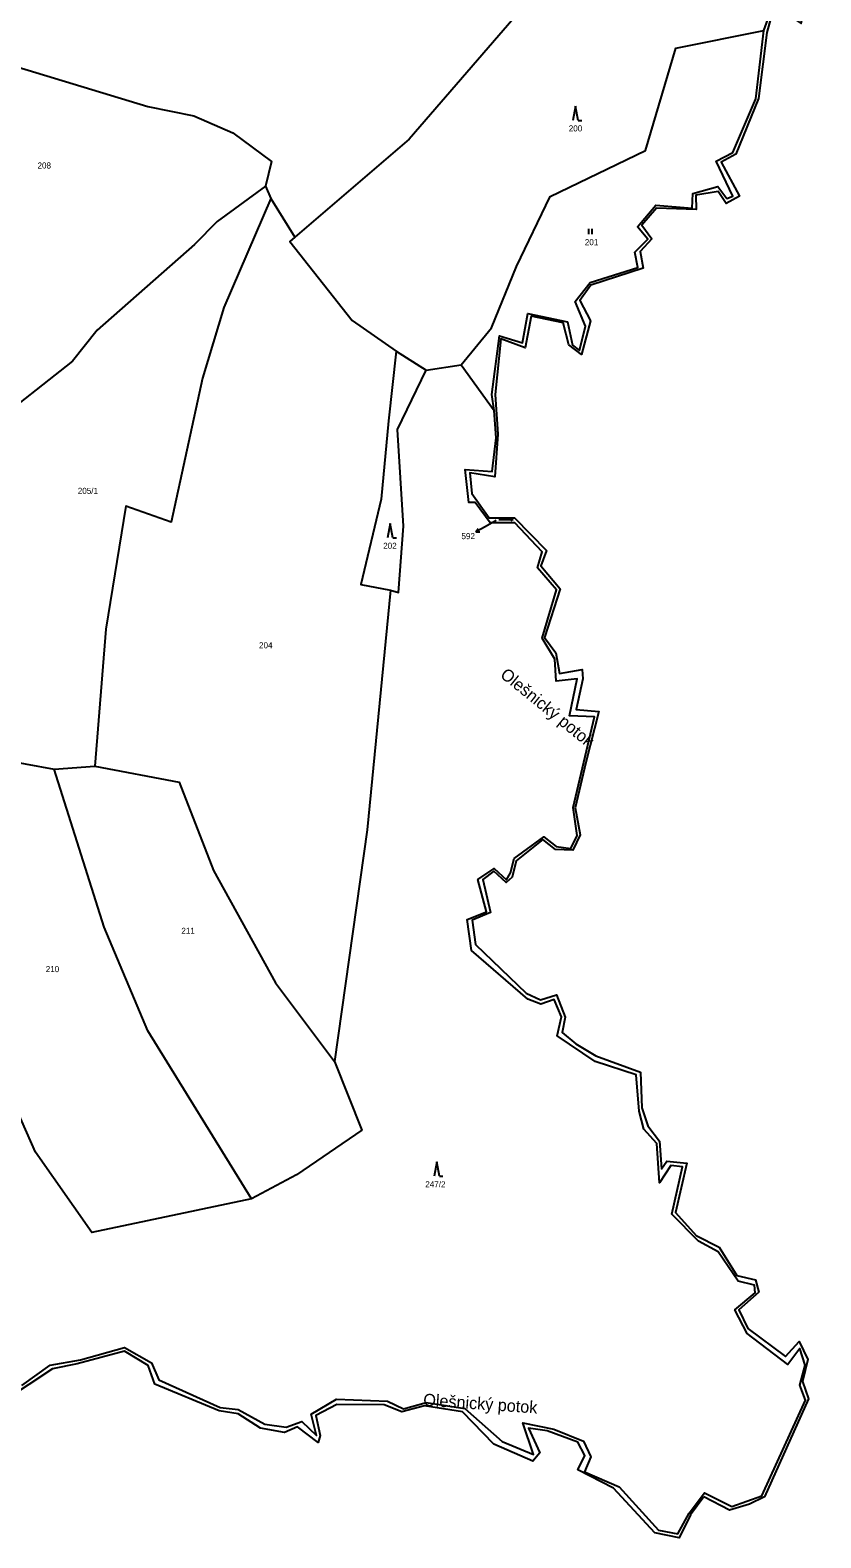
# Model space of a CAD drawing. Extents: x -680203 to -673936, y -1102717 to -1093650.
# Drawn here: x -674938.8 to -674716.8, y -1101515 to -1101091.6 of the extents above; entities that cross this region are included whole.
import ezdxf

# ---------------------------------------------------------------- set-up
doc = ezdxf.new("R2010")
doc.units = 0
for name, color, linetype in [('SOxx02xx_Staničení_Popis10', 7, 'Continuous'), ('SOxxxxxx_Koleje_hlavní_body_Popis10', 7, 'Continuous'), ('SOxxxxxx_Osa_bod_P', 7, 'Continuous'), ('x_prac', 7, 'Continuous')]:
    doc.layers.add(name, color=color, linetype=linetype)

msp = doc.modelspace()

# ---------------------------------------------------------------- linework, layer by layer
at = {"layer": 'SOxx02xx_Staničení_Popis10'}
for p, q in [((-674811.06, -1101231.09), (-674813.69, -1101232.54)), ((-674813.69, -1101232.54), (-674813.05, -1101231.62)), ((-674813.69, -1101232.54), (-674812.57, -1101232.5)), ((-674807.97, -1101229.35), (-674811.06, -1101231.09))]:
    msp.add_line(p, q, dxfattribs=at)
at = {"layer": 'SOxxxxxx_Koleje_hlavní_body_Popis10'}
for p, q in [((-674785.63, -1101112.96), (-674786.38, -1101116.96)), ((-674784.88, -1101116.96), (-674785.63, -1101112.96)), ((-674784.88, -1101116.96), (-674783.88, -1101116.96)), ((-674781.95, -1101148.89), (-674781.95, -1101147.39)), ((-674780.95, -1101148.89), (-674780.95, -1101147.39)), ((-674803.19, -1101229.06), (-674803.84, -1101228.72)), ((-674837.7, -1101230.16), (-674838.45, -1101234.16)), ((-674836.95, -1101234.16), (-674837.7, -1101230.16)), ((-674807.21, -1101229.06), (-674803.19, -1101229.06)), ((-674803.19, -1101229.06), (-674803.84, -1101229.39)), ((-674836.95, -1101234.16), (-674835.95, -1101234.16)), ((-674824.64, -1101409.46), (-674825.39, -1101413.46)), ((-674823.89, -1101413.46), (-674824.64, -1101409.46)), ((-674823.89, -1101413.46), (-674822.89, -1101413.46))]:
    msp.add_line(p, q, dxfattribs=at)
at = {"layer": 'x_prac'}
for p, q in [((-674872.74, -1101135.46), (-674871.19, -1101138.94)), ((-674871.19, -1101138.94), (-674864.52, -1101149.8)), ((-674836.04, -1101181.74), (-674827.63, -1101187.12)), ((-674827.63, -1101187.12), (-674817.74, -1101185.66)), ((-674817.74, -1101185.66), (-674808.52, -1101198.44)), ((-674951.6, -1101295.63), (-674932.08, -1101299.12)), ((-674932.08, -1101299.12), (-674920.66, -1101298.28))]:
    msp.add_line(p, q, dxfattribs=at)
for points in [[(-674756.74, -1101041.91), (-674780.78, -1101062.54), (-674832.35, -1101122.28), (-674864.52, -1101149.8)], [(-674732.81, -1101091.71), (-674730.19, -1101084.52), (-674722.31, -1101089.75), (-674720.57, -1101081.13), (-674716.77, -1101075.16), (-674725.16, -1101064.7)], [(-674975.68, -1101083.92), (-674947.76, -1101100.39), (-674905.79, -1101113.05), (-674892.85, -1101115.7), (-674881.92, -1101120.5), (-674871.01, -1101128.49), (-674872.74, -1101135.46)], [(-674730.15, -1101085.86), (-674731.92, -1101092.32), (-674734.26, -1101110.79), (-674740.66, -1101126.44), (-674744.77, -1101128.73), (-674739.57, -1101138.27), (-674743.39, -1101140.28), (-674745.56, -1101136.99), (-674751.84, -1101137.97), (-674751.78, -1101141.99), (-674762.9, -1101141.59), (-674767.07, -1101146.44), (-674764.24, -1101150.25), (-674767.5, -1101153.78), (-674766.67, -1101158.5), (-674781.39, -1101163.23), (-674784.5, -1101167.52), (-674781.45, -1101173.28), (-674783.95, -1101182.76), (-674787.51, -1101180.02), (-674789.16, -1101173.8), (-674798.15, -1101171.98), (-674799.82, -1101180.81), (-674806.62, -1101178.31), (-674808.2, -1101193.98), (-674807.44, -1101205.07), (-674808.29, -1101217.04), (-674815.32, -1101215.94), (-674814.81, -1101221.79), (-674809.93, -1101228.62), (-674802.77, -1101228.54), (-674793.78, -1101237.75), (-674795.42, -1101242.05), (-674790.02, -1101248.49), (-674794.38, -1101262.16), (-674791.18, -1101266.52), (-674790.12, -1101272.29), (-674783.8, -1101271.14), (-674783.62, -1101273.8), (-674785.47, -1101282.44), (-674779.16, -1101283), (-674782.78, -1101297.32), (-674785.77, -1101309.99), (-674784.35, -1101317.64), (-674786.43, -1101321.88), (-674791.26, -1101321.73), (-674794.85, -1101318.89), (-674802.37, -1101324.92), (-674803.44, -1101329.52), (-674805.12, -1101330.96), (-674808.56, -1101327.85), (-674811.7, -1101330.14), (-674809.5, -1101339.37), (-674814.66, -1101341.55), (-674813.79, -1101348.4), (-674799.53, -1101362.03), (-674795.53, -1101363.98), (-674791.02, -1101362.55), (-674788.58, -1101368.79), (-674789.46, -1101373.09), (-674785.56, -1101376.26), (-674779.98, -1101379.64), (-674767.46, -1101384.24), (-674767.05, -1101394.26), (-674765.38, -1101399.35), (-674762.08, -1101403.67), (-674761.5, -1101411.38), (-674760.04, -1101409.22), (-674754.45, -1101409.77), (-674757.59, -1101423.63), (-674751.77, -1101430.08), (-674745.37, -1101433.4), (-674740.37, -1101441.39), (-674735.13, -1101442.6), (-674734.19, -1101446.07), (-674739.79, -1101451.01), (-674737.26, -1101456.25), (-674726.68, -1101464.05), (-674722.87, -1101459.86), (-674720.4, -1101464.9), (-674721.95, -1101471.15), (-674720.24, -1101475.96), (-674732.61, -1101503.53), (-674736.81, -1101505.52), (-674742.38, -1101507.23), (-674749.67, -1101503.51)], [(-674817.74, -1101185.66), (-674809.24, -1101175.25), (-674802.24, -1101158), (-674792.75, -1101138.34), (-674766.06, -1101125.42), (-674757.48, -1101096.72), (-674732.81, -1101091.71)], [(-674808.52, -1101198.44), (-674809.16, -1101193.94), (-674807.01, -1101177.49), (-674800.52, -1101179.48), (-674799.08, -1101171.21), (-674787.9, -1101173.52), (-674786.55, -1101180.09), (-674784.52, -1101181.63), (-674782.85, -1101174.78), (-674785.79, -1101167.79), (-674781.52, -1101162.53), (-674768.16, -1101158.25), (-674769.02, -1101154.01), (-674765.36, -1101150.35), (-674768.24, -1101146.82), (-674763.11, -1101140.74), (-674752.92, -1101141.67), (-674752.69, -1101137.53), (-674745.68, -1101135.53), (-674743.13, -1101138.94), (-674741.48, -1101138.21), (-674746.17, -1101128.44), (-674741.46, -1101125.98), (-674735, -1101110.93), (-674732.81, -1101091.71)], [(-674872.74, -1101135.46), (-674886.33, -1101145.35), (-674892.66, -1101151.81), (-674919.96, -1101175.92), (-674926.96, -1101184.62), (-674950.49, -1101203.14)], [(-674871.19, -1101138.94), (-674884.47, -1101169.55), (-674890.45, -1101189.39), (-674899.23, -1101229.84), (-674911.96, -1101225.35), (-674917.59, -1101259.87), (-674920.66, -1101298.28)], [(-674864.52, -1101149.8), (-674865.85, -1101151.01), (-674848.35, -1101173.18), (-674836.04, -1101181.74)], [(-674836.04, -1101181.74), (-674838.2, -1101201.36), (-674840.28, -1101223.3), (-674845.98, -1101247.26), (-674837.63, -1101248.93)], [(-674837.63, -1101248.93), (-674835.4, -1101249.58), (-674833.94, -1101230.93), (-674835.66, -1101203.75), (-674827.63, -1101187.12)], [(-674941.2, -1101472.2), (-674933.16, -1101466.55), (-674924.69, -1101465.04), (-674912.3, -1101461.61), (-674904.74, -1101465.84), (-674902.64, -1101470.69), (-674885.49, -1101478.41), (-674880.36, -1101479.02), (-674872.94, -1101483.1), (-674866.94, -1101483.95), (-674862.52, -1101482.32), (-674858.43, -1101486.24), (-674859.91, -1101480.27), (-674852.83, -1101476.06), (-674838.51, -1101476.63), (-674833.97, -1101478.78), (-674827.65, -1101476.99), (-674816.77, -1101478.66), (-674806.28, -1101488), (-674797.5, -1101491.57), (-674800.47, -1101482.75), (-674791.71, -1101484.48), (-674783.47, -1101487.85), (-674781.39, -1101492.3), (-674783.14, -1101496.46), (-674773.45, -1101500.65), (-674762.32, -1101512.87), (-674756.92, -1101513.85), (-674753.74, -1101508.12), (-674749.41, -1101502.35), (-674741.81, -1101506.25), (-674733.36, -1101503.21), (-674721.06, -1101476.4), (-674722.64, -1101472.17), (-674721.14, -1101466.52), (-674722.68, -1101461.89), (-674726.06, -1101466.38), (-674737.48, -1101457.6), (-674740.97, -1101450.98), (-674735.21, -1101446.24), (-674735.42, -1101444.07), (-674739.99, -1101442.96), (-674745.61, -1101434.7), (-674751.17, -1101431.75), (-674758.63, -1101424.14), (-674755.65, -1101410.79), (-674758.9, -1101410.43), (-674762.07, -1101415.32), (-674762.84, -1101404.24), (-674766.51, -1101400.28), (-674767.83, -1101395.19), (-674768.61, -1101385.01), (-674780.15, -1101381.22), (-674790.86, -1101374.04), (-674789.59, -1101368.71), (-674791.63, -1101363.8), (-674795.42, -1101365.12), (-674799.07, -1101363.77), (-674814.91, -1101350.06), (-674816.1, -1101341.38), (-674810.62, -1101339.25), (-674813.13, -1101330.17), (-674808.53, -1101327.07), (-674805.07, -1101330.23), (-674803.92, -1101328.32), (-674802.94, -1101324.24), (-674794.61, -1101318.18), (-674791.11, -1101320.89), (-674786.99, -1101321.48), (-674785.23, -1101317.81), (-674786.32, -1101309.92), (-674780.36, -1101284.47), (-674787.34, -1101284.15), (-674785.24, -1101273.84), (-674791.1, -1101274.45), (-674791.48, -1101268.23), (-674795.07, -1101262.35), (-674790.98, -1101248.82), (-674796.31, -1101242.66), (-674795.01, -1101238.09), (-674802.75, -1101229.98), (-674809.65, -1101230.03), (-674813.86, -1101224.3), (-674815.61, -1101224.26), (-674816.61, -1101214.99), (-674809.06, -1101215.56), (-674807.91, -1101206.16), (-674808.52, -1101198.44)], [(-674837.63, -1101248.93), (-674844.2, -1101316.23), (-674853.35, -1101381.26)], [(-674876.64, -1101419.78), (-674905.78, -1101372.67), (-674918.03, -1101343.52), (-674932.08, -1101299.12)], [(-674920.66, -1101298.28), (-674896.97, -1101302.78), (-674887.29, -1101327.66), (-674869.94, -1101359.15), (-674853.35, -1101381.26)], [(-674876.64, -1101419.78), (-674921.51, -1101429.31), (-674937.31, -1101406.76), (-674958.1, -1101359.86), (-674966.06, -1101334.16), (-674963.46, -1101321.18)], [(-674853.35, -1101381.26), (-674845.71, -1101400.53), (-674864.07, -1101413.11), (-674876.64, -1101419.78)], [(-674749.67, -1101503.51), (-674753.4, -1101508.58), (-674756.58, -1101515.02), (-674763.39, -1101513.61), (-674775, -1101501.06), (-674785.06, -1101495.95), (-674783.02, -1101491.91), (-674785.06, -1101488.12), (-674793.62, -1101484.95), (-674798.91, -1101484.19), (-674795.71, -1101491.11), (-674797.64, -1101493.48), (-674808.65, -1101488.73), (-674817.38, -1101479.62), (-674828.04, -1101477.94), (-674834.41, -1101479.6), (-674839.38, -1101477.71), (-674852.68, -1101477.54), (-674858.63, -1101480.67), (-674857.4, -1101486.31), (-674857.95, -1101488.25), (-674863.76, -1101483.83), (-674867.37, -1101485.47), (-674874.16, -1101484.22), (-674880.44, -1101480.2), (-674885.71, -1101479.35), (-674903.82, -1101471.82), (-674905.66, -1101466.65), (-674912.33, -1101462.64), (-674925.65, -1101466.18), (-674932.54, -1101467.56), (-674945.88, -1101476.32)]]:
    msp.add_lwpolyline(points, dxfattribs=at)

# ---------------------------------------------------------------- texts
at = {"layer": 'SOxx02xx_Staničení_Popis10'}
for rotation, p in [(321, (-674807.06, -1101273.11)), (356, (-674828.51, -1101477.88))]:
    msp.add_text('Olešnický potok', height=3.4, rotation=rotation, dxfattribs=at).set_placement(p)
at = {"layer": 'SOxxxxxx_Osa_bod_P'}
for s, p in [('200', (-674787.57, -1101120.08)), ('208', (-674936.75, -1101130.49)), ('201', (-674783.05, -1101152.02)), ('205/1', (-674925.45, -1101221.86)), ('592', (-674817.7, -1101234.57)), ('202', (-674839.68, -1101237.28)), ('204', (-674874.55, -1101265.21)), ('211', (-674896.36, -1101345.4)), ('210', (-674934.45, -1101356.16)), ('247/2', (-674827.86, -1101416.58))]:
    msp.add_text(s, height=1.7, dxfattribs=at).set_placement(p)

doc.saveas('drawing.dxf')
